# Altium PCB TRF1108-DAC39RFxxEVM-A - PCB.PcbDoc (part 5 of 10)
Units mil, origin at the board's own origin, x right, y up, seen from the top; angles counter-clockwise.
Board outline 4951.22 x 2726.56 mil, 16 copper layers (Top Layer, L2 GND1, L3 PWR1, L4 GND2, L5 PWR2, L6 GND3, L7 Ctrl Signal 1, L8 GND4, L9 GND5, L10 Ctrl Signal 2, L11 GND6, L12 PWR3, L13 GND7, L14 PWR4, L15 GND8, Bottom Layer), stack 80.2 mil thick; 705 components, 433 nets, 3633 pads, 1678 vias.
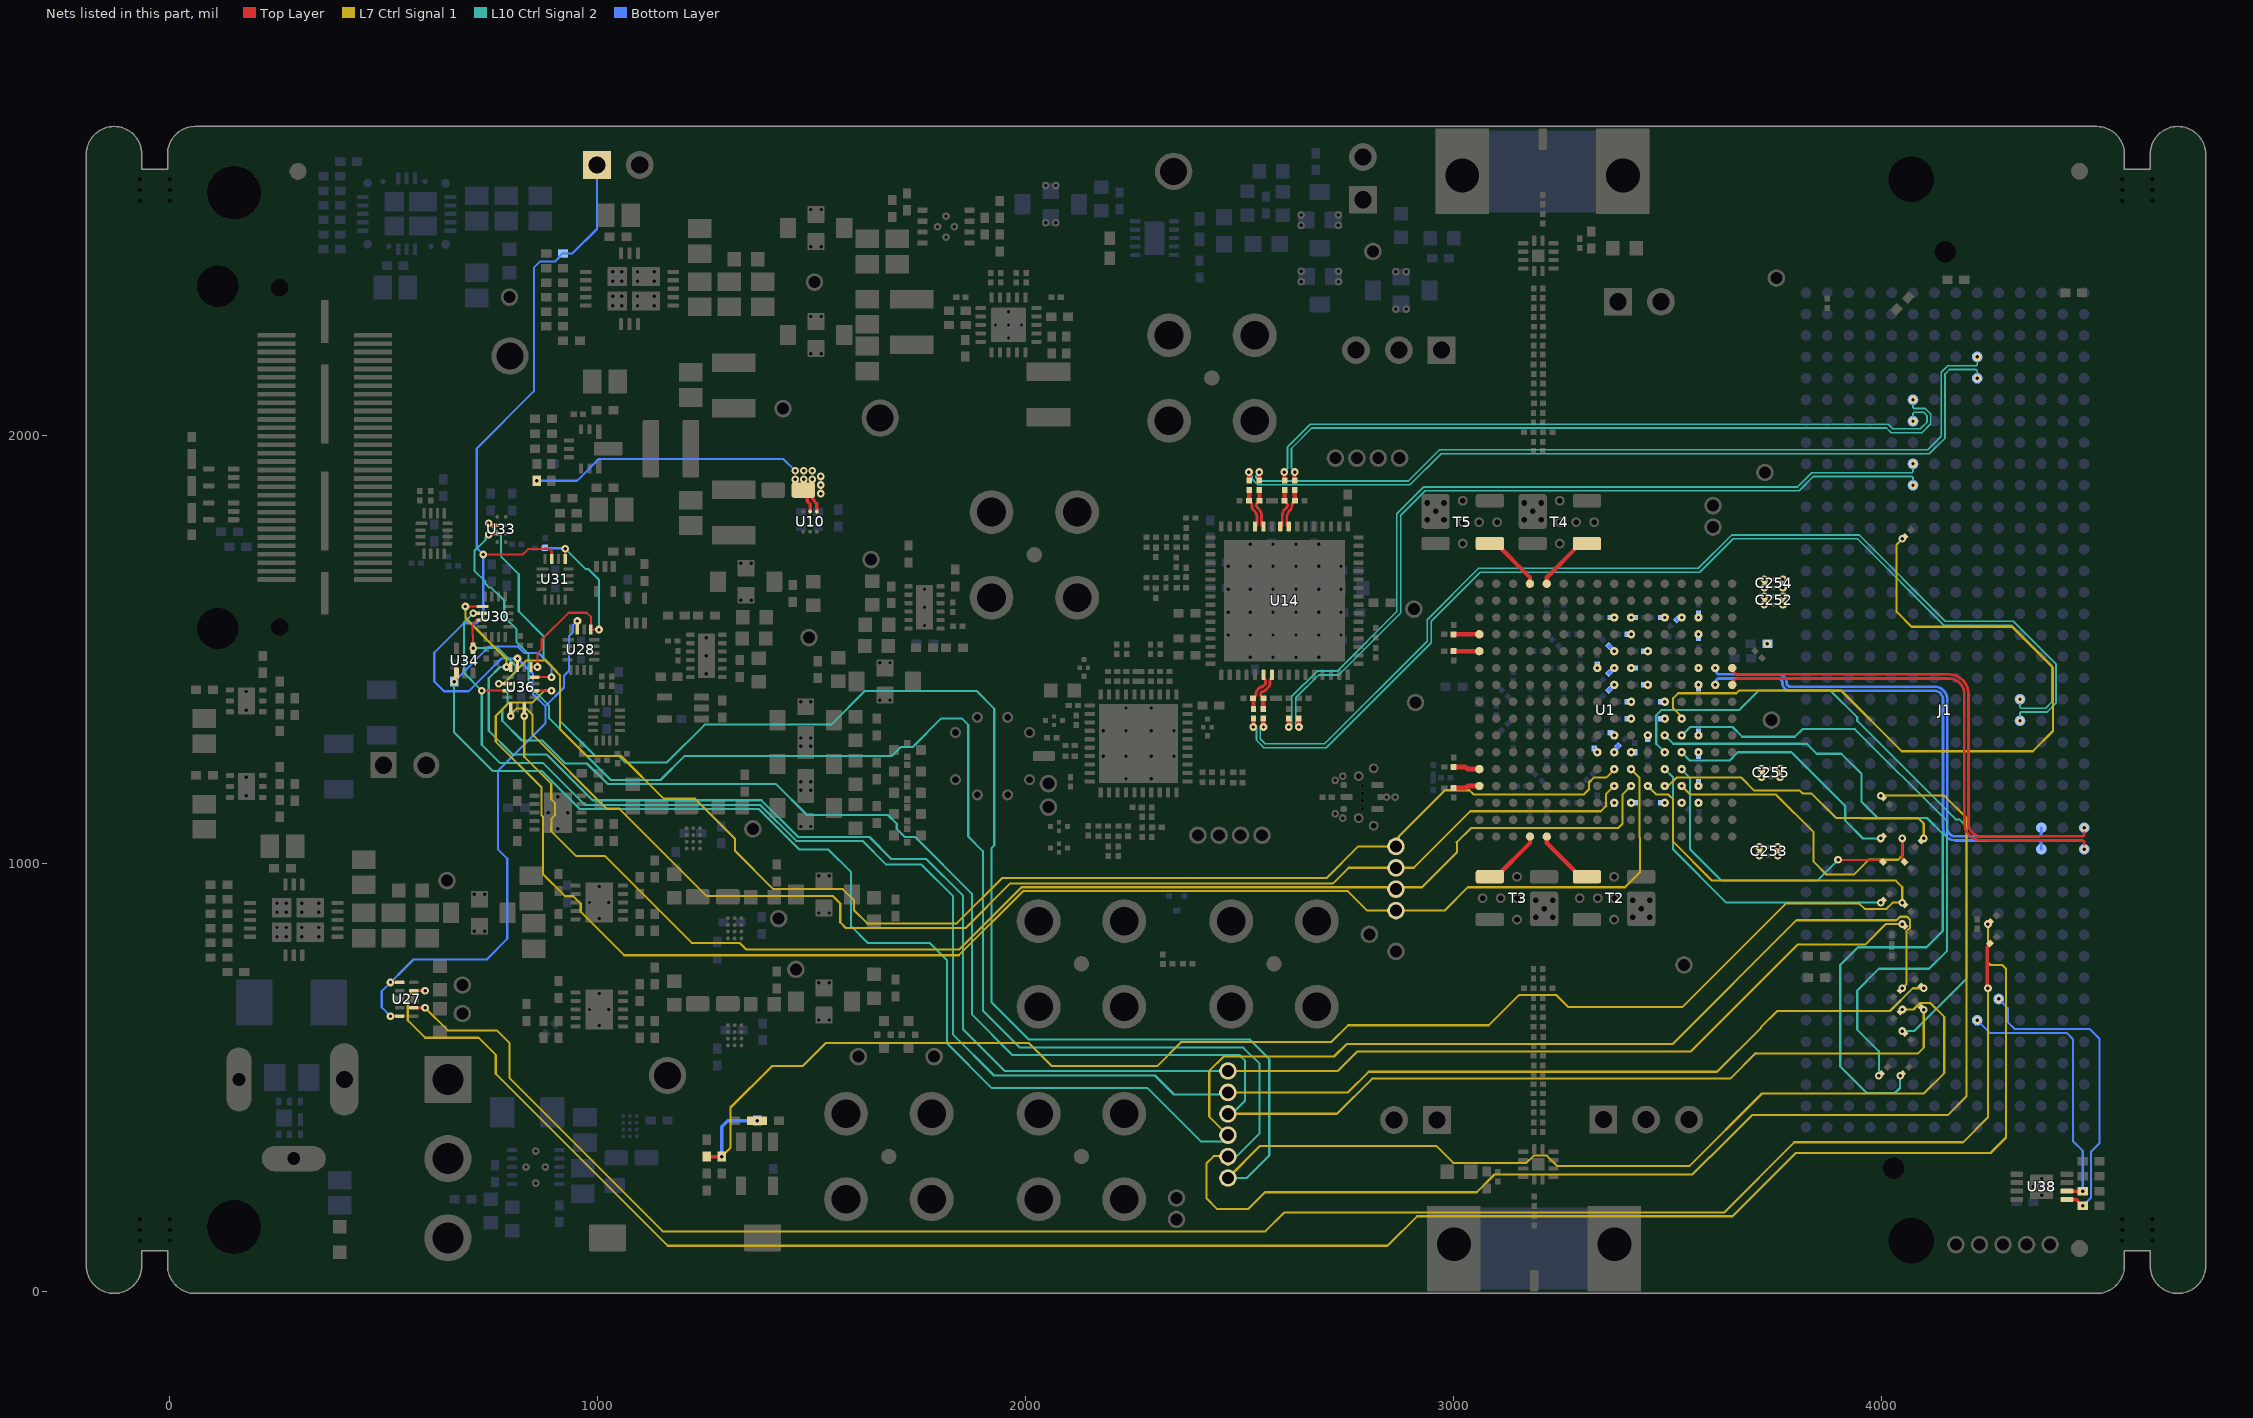
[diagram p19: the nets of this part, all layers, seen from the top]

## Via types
v1: diameter 18, hole 8, Top Layer to Bottom Layer, tented both sides, 1468 vias
v2: diameter 20, hole 10.01, Top Layer to Bottom Layer, 187 vias
v3: diameter 19.68, hole 7.87, Top Layer to Bottom Layer, tented both sides, 16 vias
v4: diameter 19.68, hole 7.87, Top Layer to Bottom Layer, 6 vias
v5: diameter 18/18/18/18/18/18/18/18/18/18/18/18/18/18/18/18 (per signal layer), hole 8, Top Layer to Bottom Layer, tented both sides, 1 vias

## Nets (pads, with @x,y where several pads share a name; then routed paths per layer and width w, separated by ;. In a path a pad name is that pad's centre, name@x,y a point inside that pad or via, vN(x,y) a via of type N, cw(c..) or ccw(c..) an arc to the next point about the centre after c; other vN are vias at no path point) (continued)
14SRX_n: J1.Y26 U1.L1 | length 1194.7
  Top Layer w6.25: U1.L1@3650.36,1456.21 ccw(c3665.17,1456.21) 3665.17,1441.4 4156.63,1441.4 cw(c4156.63,1395.6) 4202.44,1395.6 4202.44,1093.14 ccw(c4232.64,1093.14) 4232.64,1062.93 4467.73,1062.93 ccw(c4467.73,1068.01) 4472.81,1068.01 v1(4472.81,1083.06)
14SRX_p: J1.Y27 U1.K1 | length 1194
  Top Layer w6.25: U1.K1@3650.36,1416.84 cw(c3665.17,1416.84) 3665.17,1431.65 4156.63,1431.65 cw(c4156.63,1395.6) 4192.69,1395.6 4192.69,1116.68 ccw(c4256.18,1116.68) 4193.14,1109.05 cw(c4186.94,1108.34) 4193.19,1108.37 4193.19,1093.14 ccw(c4232.64,1093.14) 4232.64,1053.68 4247.88,1053.68 cw(c4247.85,1047.43) 4248.56,1053.64 ccw(c4256.18,1116.68) 4256.18,1053.18 4467.73,1053.18 cw(c4467.73,1048.1) 4472.81,1048.1 v1(4472.81,1033.06)
15SRX_n: J1.A26 U1.L2 | length 1133.4
  Bottom Layer w6.25: v1(3610.99,1456.21) cw(c3605.56,1450.79) 3613.24,1450.79 3613.24,1447.81 ccw(c3619.64,1447.81) 3615.11,1443.28 ccw(c3619.64,1447.81) 3619.64,1441.4 3757.54,1441.4 cw(c3757.54,1421.3) 3777.64,1421.3 ccw(c3786.15,1421.3) 3786.15,1412.79 4122.81,1412.79 cw(c4122.81,1383.07) 4152.53,1383.07 4152.53,1083.06 ccw(c4172.65,1083.06) 4172.65,1062.93 4363.97,1062.93 ccw(c4363.97,1071.77) 4372.81,1071.77 J1.A26@4372.81,1083.06
15SRX_p: J1.A27 U1.K2 | length 1133.4
  Bottom Layer w6.25: v1(3610.99,1416.84) ccw(c3605.56,1422.27) 3613.24,1422.27 3613.24,1425.25 cw(c3619.64,1425.25) 3615.11,1429.78 cw(c3619.64,1425.25) 3619.64,1431.65 3757.54,1431.65 cw(c3757.54,1421.3) 3767.89,1421.3 ccw(c3786.15,1421.3) 3786.15,1403.04 4122.81,1403.04 cw(c4122.81,1383.07) 4142.78,1383.07 4142.78,1083.06 ccw(c4172.65,1083.06) 4172.65,1053.18 4363.97,1053.18 cw(c4363.97,1044.34) 4372.81,1044.34 J1.A27@4372.81,1033.06
COMM_MUX_CTRL: J12.1 R161.1 U27.1 U27.5 U28.15 U31.15 U36.15 | length 3290.5
  Top Layer w5: v1(515.88,642.95) U27.5@537.69,642.95 ; v1(515.88,721.7) U27.1@537.69,721.7 ; v1(732.62,1721.42) 825.06,1721.42 837.6,1733.97 886.77,1733.97 892.57,1728.16 U31.15@892.57,1711.04 ; U28.15@952.57,1546.04 v1(952.57,1566.04)
  Bottom Layer w5: v1(515.88,642.95) 495.4,663.44 495.4,701.21 569.45,775.27 740.44,775.27 788.49,823.32 788.49,1010.8 766.73,1032.55 766.73,1215.72 877.57,1326.56 877.57,1366.89 ; v1(952.57,1566.04) 942.32,1555.79 942.32,1539.62 932.89,1530.18 932.89,1449.53 921.32,1437.97 921.32,1410.88 877.57,1367.13 877.57,1366.89 ; J12.1@998.12,2631.37 998.12,2481.96 940.79,2424.63 R161.1@919.01,2424.63 917.04,2424.63 909.7,2417.29 909.7,2415.32 900.67,2406.29 865.51,2406.29 850.92,2391.69 850.92,2102.75 717.41,1969.25 717.41,1736.63 v1(732.62,1721.42) 732.62,1576.25 717.18,1560.81 687.05,1560.81 618.06,1491.83 618.06,1424.68 640.74,1402.01 698.41,1402.01 752.45,1456.04 752.54,1456.04 775.04,1478.54 v1(812.57,1478.54) 848.95,1442.16 848.95,1395.51 877.57,1366.89
COMM_MUX_EN: R159.1 R162.2 U28.13 U31.13 U36.13 | length 579.8
  Top Layer w5: U36.13@844.07,1458.54 v1(859.07,1458.54) 859.07,1490.07 869.3,1500.3 869.3,1522.88 931.91,1585.49 974.7,1585.49 984.07,1576.12 U28.13@984.07,1546.04 v1(1003,1546.04) ; v1@921.14,1738.04 v1(924.07,1735.11) U31.13@924.07,1711.04
  L10 Ctrl Signal 2 w5: v1(924.07,1735.11) 972.01,1687.17 978.36,1687.17 1003,1662.52 v1(1003,1546.04)
  Bottom Layer w5: R159.1@875.57,1736.04 923.14,1736.04 v1(924.07,1735.11)
DAC_ALARM: R209.1 U1.H4 | length 1772.9
  Top Layer w5: R209.1@4047.5,1757.75 v1(4047.81,1758.06)
  L7 Ctrl Signal 1 w5: v1(3532.25,1338.1) 3532.25,1341.62 3527.65,1346.22 3527.65,1346.84 3512.48,1362.01 3512.48,1385.59 3524.13,1397.24 3660.24,1397.24 3666.78,1403.79 3904.73,1403.79 4046.68,1261.84 4352.8,1261.84 4400,1309.04 4400,1456.62 4303.96,1552.66 4069.38,1552.66 4034.47,1587.57 4034.47,1744.71 v1(4047.81,1758.06)
DAC_C\S\: PP38.1 U1.E7 U36.10 | length 3629.7
  Top Layer w5: U36.10@851.94,1403.42 v1(891.94,1403.42)
  L7 Ctrl Signal 1 w5: v1(891.94,1403.42) 875.44,1403.41 847.89,1375.86 793.35,1375.86 761.73,1344.24 761.73,1284.15 868.91,1176.96 868.91,1112.07 871.94,1109.04 871.94,975.03 924.01,922.96 942.81,922.96 960.24,905.53 960.24,886.74 1061.87,785.11 1843.75,785.11 1993.73,935.08 2752.17,935.08 2797.78,889.47 PP38.1@2864.85,889.47 2978.41,889.47 3032.97,944.03 3400.03,944.03 3435,979 3435,1060 ; v1(3414.14,1219.99) 3433.91,1200.22 3433.91,1188.74 3433.74,1188.57 3433.74,1060
DAC_CIPO: PP37.1 U1.D7 U36.7 | length 3171.6
  Top Layer w5: v1(828.32,1344.05) U36.7@828.32,1364.05
  L7 Ctrl Signal 1 w5: v1(828.32,1344.05) 828.32,1249 891.55,1185.77 891.55,1149.47 899.79,1141.24 899.79,1112.07 891.94,1104.22 891.94,1087.85 891.55,1087.46 891.55,1074.67 948.95,1017.27 1016.37,1017.27 1219.54,814.11 1331.22,814.11 1346.89,798.43 1844.35,798.43 1990,944.08 2925.53,944.08 3007.54,1026.09 3007.54,1049 ; 3007,1049 3040.11,1082.11 3383.77,1082.11 3394.54,1092.88 3394.54,1161.02 v1(3414.14,1180.62)
DAC_CLK_n: C135.2 C140.1 U1.E16 | length 61.3
  Top Layer w11.5: C135.2@2999.81,1224.99 3024.49,1224.99 cw(c3024.49,1218.67) 3028.96,1223.14 ccw(c3036.56,1230.74) 3036.56,1219.99 U1.E16@3059.81,1219.99
DAC_CLK_p: C134.2 C138.1 U1.D16 | length 61.3
  Top Layer w11.5: C134.2@2999.81,1175.62 3024.49,1175.62 ccw(c3024.49,1181.94) 3028.96,1177.47 cw(c3036.56,1169.87) 3036.56,1180.62 U1.D16@3059.81,1180.62
DAC_COPI: PP36.1 U1.D8 U36.5 | length 3028.6
  Top Layer w5: v1(796.82,1344.05) U36.5@796.82,1364.05
  L7 Ctrl Signal 1 w5: v1(796.82,1344.05) cw(c807.09,1344.05) 799.83,1351.31 810.5,1361.98 832.31,1361.98 847.99,1346.3 847.99,1300.01 1020.53,1127.46 1050.27,1127.46 1253.73,924 1548.65,924 1566.49,906.16 1566.49,862.1 1579.98,848.62 1859.36,848.62 1963.82,953.08 2718.01,953.08 2754.4,989.47 PP36.1@2864.85,989.47 2906.33,989.47 3038.52,1121.65 3343.52,1121.65 3355.17,1133.3 3355.17,1161.17 v1@3376,1182
  other v1: 3374.77,1180.62
DAC_R\E\S\E\T\: C171.2 R170.1 R171.1 R173.1 R174.1 R220.1 U1.D6 | length 4141
  Top Layer w5: v1@4047.5,908.36 v1(4047.81,908.06)
  Top Layer w8: R170.1@1254.63,314.72 v1(1289.63,314.72) ; R174.1@1360.42,398.96 R173.1@1384.04,398.96
  L7 Ctrl Signal 1 w5: v1(1289.63,314.72) 1310.37,335.46 1310.37,429.37 1407.2,526.2 1478.3,526.2 1532.42,580.32 2007.23,580.32 2061.35,526.2 2307.22,526.2 2363.34,582.32 2713.8,582.32 2753.24,621.76 3081.76,621.76 3152,692 3240,692 3268,664 3534,664 3775.67,905.67 3947.63,905.67 3959.74,893.56 4010.8,893.56 4025.3,908.06 v1(4047.81,908.06) 4047.81,944.01 4032.35,959.46 3603.16,959.46 3512.48,1050.15 3512.48,1149.37 3501,1160.85 3473.28,1160.85 v1(3453.51,1180.62)
  Bottom Layer w8: v1(1289.63,314.72) 1289.63,384.84 1303.74,398.96 v1(1372.23,398.96)
DAC_SCLK: PP35.1 U1.E8 U36.2 | length 3184.4
  Top Layer w5: v1(768.95,1419.17) U36.2@788.95,1419.17
  L7 Ctrl Signal 1 w5: v1(768.95,1419.17) 770.74,1420.95 780.5,1420.95 833.58,1474.04 878.16,1474.04 900.73,1451.47 900.73,1450.41 911.59,1439.56 911.59,1313.67 974.47,1250.79 1054.22,1250.79 1154.2,1150.81 1227.21,1150.81 1320.57,1057.46 1320.57,1029.38 1410.4,939.55 1572.83,939.55 1598.77,913.61 1598.77,890.59 1629.63,859.73 1839.11,859.73 1944.85,965.46 2703.01,965.46 2777.02,1039.47 PP35.1@2864.85,1039.47 2871.24,1045.86 2871.24,1062.47 2979.46,1170.69 3036.47,1170.69 3046.14,1161.02 3304.15,1161.02 3315.71,1172.59 3315.71,1188.66 3327.28,1200.22 3343.52,1200.22 3356.22,1200.22 3374.77,1218.77 v1(3374.77,1219.99)
DAC_SYSREF_n: C73.2 C76.1 U1.N16 | length 60
  Top Layer w10: C73.2@2999.81,1534.95 U1.N16@3059.81,1534.95
DAC_SYSREF_p: C74.2 C75.1 U1.M16 | length 60
  Top Layer w10: C74.2@2999.81,1495.58 U1.M16@3059.81,1495.58
DAC_TXEN0: R216.1 U1.D5 | length 692.5
  L7 Ctrl Signal 1 w5: v1(3492.88,1180.62) 3495.36,1183.11 3503.54,1183.11 3520.82,1200.39 3671.38,1200.39 3701.92,1169.85 3808.29,1169.85 3814.69,1163.46 3835.38,1163.46 3892.8,1106.04 3953.8,1106.04 3954.6,1105.24 4085.54,1105.24 4097.81,1092.98 v1(4097.81,1058.06)
DAC_TXEN1: R218.1 U1.D4 | length 757
  Top Layer w5: 4047.5,1008.36 R218.1@4047.81,1008.06 ; v1(4047.81,1058.06) 4047.81,1013.24 4052.52,1008.54 R218.1@4052.52,1003.35
  L7 Ctrl Signal 1 w5: v1(3532.25,1180.62) 3552.02,1160.85 3752.25,1160.85 3840.58,1072.52 3840.58,1003.9 3870.9,973.59 3934.46,973.59 3969.14,1008.27 4038.03,1008.27 4047.81,1018.04 v1(4047.81,1058.06)
DACOUTA_n: T3.1 U1.A13 | length 141.4
  Top Layer w10: T3.1@3084.22,968.59 3098.99,968.59 3177.92,1047.51 U1.A13@3177.92,1062.51
DACOUTA_p: T2.1 U1.A12 | length 141.4
  Top Layer w10: U1.A12@3217.29,1062.51 3217.29,1047.51 3296.21,968.59 T2.1@3310.99,968.59
DACOUTB_n: T5.1 U1.T13 | length 141.4
  Top Layer w10: T5.1@3084.22,1746.99 3098.99,1746.99 3177.92,1668.06 U1.T13@3177.92,1653.06
DACOUTB_p: T4.1 U1.T12 | length 141.4
  Top Layer w10: U1.T12@3217.29,1653.06 3217.29,1668.06 3296.21,1746.99 T4.1@3310.99,1746.99
DCLKOUT2_n: C91.2 R75.2 U14.55 | length 92.7
  Top Layer w6.5: R75.2@2555.71,1385.46 cw(c2555.71,1387.37) 2554.37,1386.02 2550.83,1389.56 cw(c2555.96,1394.7) 2548.7,1394.7 cw(c2555.96,1394.7) 2550.83,1399.83 2550.9,1399.9 cw(c2554.78,1396.02) 2554.78,1401.51 ccw(c2554.78,1407.01) 2558.66,1403.12 2567.35,1411.81 ccw(c2559.97,1419.19) 2570.41,1419.19 2570.41,1425.73 cw(c2578.25,1425.73) 2572.71,1431.28 ccw(c2567.16,1436.82) 2575,1436.82 U14.55@2575,1440.46
  Top Layer w10: C91.2@2554.93,1360.46 R75.2@2554.93,1383.56
DCLKOUT2_p: C90.2 R74.2 U14.54 | length 92.8
  Top Layer w6.5: R74.2@2531.19,1385.46 ccw(c2531.19,1387.37) R74.2@2532.52,1386.02 ; R74.2@2532.53,1386.02 2535.09,1388.58 ccw(c2527.57,1396.09) 2538.2,1396.09 2538.2,1396.87 cw(c2550.71,1396.87) 2541.85,1405.71 ; 2541.86,1405.72 2546.55,1410.4 cw(c2550.43,1406.52) 2550.43,1412.01 ccw(c2550.43,1417.51) 2554.31,1413.62 2559.91,1419.22 2559.91,1425.73 ccw(c2552.07,1425.73) 2557.61,1431.28 cw(c2563.16,1436.82) 2555.32,1436.82 U14.54@2555.32,1440.46
  Top Layer w10: C90.2@2531.97,1360.46 R74.2@2531.97,1383.56
DCLKOUT4_n: C85.2 R79.2 U14.25 | length 94.5
  Top Layer w6.5: U14.25@2594.69,1786.92 ccw(c2594.69,1791.51) 2599.28,1791.51 2599.28,1812.62 cw(c2619.74,1812.62) 2605.27,1827.09 2608.62,1830.44 ccw(c2602.22,1836.83) 2611.27,1836.83 ccw(c2602.22,1836.83) R79.2@2608.63,1843.22 ; R79.2@2604.14,1846.92 cw(c2604.14,1845.02) R79.2@2605.48,1846.37 ; R79.2@2605.48,1846.36 R79.2@2608.62,1843.23
  Top Layer w10: R79.2@2604.14,1846.92 ccw(c2602.24,1848.82) 2604.92,1848.82 C85.2@2604.92,1871.92
DCLKOUT4_p: C84.2 R78.2 U14.24 | length 94.2
  Top Layer w6.5: U14.24@2614.37,1786.92 cw(c2614.37,1791.51) 2609.78,1791.51 2609.78,1808.27 cw(c2630.24,1808.27) 2615.77,1822.74 2617.58,1824.55 ccw(c2607.47,1834.66) 2621.77,1834.66 2621.77,1836.09 cw(c2632.59,1836.09) 2624.94,1843.75 R78.2@2627.55,1846.36 ; R78.2@2627.56,1846.37 cw(c2628.9,1845.02) R78.2@2628.9,1846.92
  Top Layer w10: C84.2@2628.11,1871.92 2628.11,1848.82 ccw(c2630.8,1848.82) R78.2@2628.9,1846.92
DCLKOUT6_n: C87.2 R81.2 U14.28 | length 89.5
  Top Layer w6.5: R81.2@2525.07,1843.75 cw(c2517.41,1836.09) 2528.24,1836.09 2528.24,1834.66 ccw(c2542.54,1834.66) 2532.43,1824.55 2534.23,1822.74 cw(c2519.76,1808.27) 2540.23,1808.27 2540.23,1791.51 cw(c2535.63,1791.51) U14.28@2535.63,1786.92
  Top Layer w10: C87.2@2521.9,1871.92 2521.9,1847.7 ccw(c2523.78,1847.7) R81.2@2522.44,1846.38
DCLKOUT6_p: C86.2 R80.2 U14.27 | length 94.5
  Top Layer w6.5: R80.2@2544.53,1846.36 2541.38,1843.22 ccw(c2547.79,1836.83) 2538.74,1836.83 ccw(c2547.79,1836.83) 2541.39,1830.44 2544.73,1827.09 cw(c2530.26,1812.62) 2550.73,1812.62 2550.73,1791.51 ccw(c2555.32,1791.51) U14.27@2555.32,1786.92 ; R80.2@2544.53,1846.37 cw(c2545.87,1845.02) R80.2@2545.87,1846.92
  Top Layer w10: C86.2@2545.08,1871.92 cw(c2543.18,1870.02) 2545.87,1870.02 R80.2@2545.87,1846.92
DVDD: C190.2 C191.2 C192.2 C193.2 C194.2 C195.2 C196.2 C197.2 C198.2 C199.2 C200.2 C201.2 C202.2 C203.2 C204.2 C205.2 C206.2 C207.2 C208.2 C209.2 C210.2 C211.2 C212.2 C227.2 C228.2 C229.2 C230.2 C231.2 C232.2 C233.2 C234.2 C235.2 C252.1 C252.3 C253.1 C253.3 C254.1 C254.3 C255.1 C255.3 R36.1 R40.2 R45.2 U1.C3 U1.C4 U1.C5 U1.C7 U1.C8 U1.D3 U1.F3 U1.F7 U1.F8 U1.F9 U1.G3 U1.G6 U1.G8 U1.H5 U1.H7 U1.J5 U1.J7 U1.K3 U1.K6 U1.K8 U1.L3 U1.L7 U1.L8 U1.L9 U1.M6 U1.M8 U1.N3 U1.N7 U1.P3 U1.P4 U1.P5 U1.P7 U1.P8 U10.D1 U10.D2 | length 1226.2
  Top Layer w8: U10.D2@1496.1,1821.8 1496.1,1839.1 1489.49,1845.71 1489.49,1862.66 R36.1@1480.35,1871.8 1488.06,1871.8 1502.02,1857.84 1502.02,1850.14 1511.85,1840.31 U10.D1@1511.85,1821.8
  Top Layer w10: v1(3713.63,1018.04) 3714.72,1019.14 3714.72,1027.14 C253.3@3715.63,1028.04 3714.72,1028.95 3714.72,1036.95 v1(3713.63,1038.04) ; v1(3718.93,1201.1) 3720.02,1202.19 3720.02,1210.19 C255.3@3720.93,1211.1 3720.02,1212 3720.02,1220 v1(3718.93,1221.1) ; v1(3725.49,1604.22) 3726.59,1605.31 3726.59,1613.31 C252.3@3727.49,1614.22 3726.59,1615.12 3726.59,1623.12 v1(3725.49,1624.22) ; v1(3725.49,1643.9) 3726.59,1645 3726.59,1653 C254.3@3727.49,1653.9 3726.59,1654.81 3726.59,1662.81 v1(3725.49,1663.9) ; v1(3757,1018.04) 3755.9,1019.14 3755.9,1027.14 C253.1@3755,1028.04 3755.9,1028.95 3755.9,1036.95 v1(3757,1038.04) ; v1(3762.3,1201.1) 3761.2,1202.19 3761.2,1210.19 C255.1@3760.3,1211.1 3761.2,1212 3761.2,1220 v1(3762.3,1221.1) ; v1(3768.86,1604.22) 3767.77,1605.31 3767.77,1613.31 C252.1@3766.86,1614.22 3767.77,1615.12 3767.77,1623.12 v1(3768.86,1624.22) ; v1(3768.86,1643.9) 3767.77,1645 3767.77,1653 C254.1@3766.86,1653.9 3767.77,1654.81 3767.77,1662.81 v1(3768.86,1663.9)
  Bottom Layer w5: v1(857.91,1893.82) 951.95,1893.82 1002.58,1944.45 1433.71,1944.45 v1(1461.35,1916.8) ; C200.2@3328.4,1268.02 3335.4,1261.02 v1(3335.4,1259.36) ; v1(3335.4,1456.21) C196.2@3335.4,1464.87 ; C201.2@3366.1,1298.73 v1(3374.77,1298.73) ; C235.2@3366.11,1574.32 v1(3374.77,1574.32) ; C228.2@3405.48,1338.1 v1(3414.14,1338.1) ; C194.2@3405.48,1377.47 v1(3414.14,1377.47) ; C232.2@3405.48,1534.95 v1(3414.14,1534.95) ; v1(3414.14,1141.25) C210.2@3422.8,1141.25 ; v1(3414.14,1259.36) C192.2@3420.74,1259.36 ; v1(3414.14,1456.21) C230.2@3422.8,1456.21 ; v1(3414.14,1574.32) C199.2@3422.8,1574.32 ; C203.2@3444.85,1416.84 v1(3453.51,1416.84) ; C195.2@3444.85,1495.58 v1(3453.51,1495.58) ; C193.2@3453.51,1290.07 v1(3453.51,1298.73) ; C208.2@3484.22,1141.25 v1(3492.88,1141.25) ; C229.2@3484.22,1338.1 v1(3492.88,1338.1) ; C202.2@3484.22,1377.47 v1(3492.88,1377.47) ; C234.2@3484.22,1574.32 v1(3492.88,1574.32) ; v1(3571.62,1141.25) C211.2@3573.62,1141.25 ; v1(3571.62,1180.62) C212.2@3571.62,1189.28 ; C207.2@3571.62,1250.7 v1(3571.62,1259.36) ; v1(3571.62,1298.73) C206.2@3571.62,1307.39 ; C209.2@3571.62,1408.18 v1(3571.62,1416.84) ; C197.2@3571.62,1526.29 v1(3571.62,1534.95) ; v1(3571.62,1574.32) C233.2@3571.62,1582.99
  Bottom Layer w10: C204.2@3362.88,1404.95 v1(3374.77,1416.84) ; C231.2@3362.88,1444.32 v1(3374.77,1456.21) ; C205.2@3362.88,1507.47 v1(3374.77,1495.58) ; v1(3374.77,1259.36) 3376.3,1260.89 3376.3,1265.06 3383.77,1272.53 C227.2@3383.77,1274.36 ; C198.2@3521.25,1569.32 3523.09,1569.32 3526.55,1572.79 3530.72,1572.79 v1(3532.25,1574.32)
  other v1: 3374.77,1141.25 3532.25,1141.25 3571.62,1456.21 3732.72,1512.58 1521.35,1863.8 1521.35,1883.8 1461.35,1896.8 1481.35,1896.8 1501.35,1896.8 1521.35,1903.8 1481.35,1916.8 1501.35,1916.8
FMC_C\S\_DAC: PP34.1 R163.2 R225.1 U34.1 U36.12 | length 5016.1
  Top Layer w5: U36.12@851.94,1434.91 v1(891.94,1434.91) ; R225.1@4043.12,703.35 v1(4047.83,708.06)
  Top Layer w8: v1@664.58,1419.4 664.58,1422.11 669.58,1427.11 U34.1@669.58,1444.4
  L7 Ctrl Signal 1 w5: PP34.1@2472.23,364.83 2428.82,408.24 2428.82,515.12 2462.32,548.62 2720.22,548.62 2749.59,578 3511.39,578 3800.44,867.06 4034.15,867.06 4042.34,875.24 4058.71,875.24 4065.65,868.29 4065.65,849.59 4057.31,841.25 4057.31,717.54 v1(4047.83,708.06)
  L10 Ctrl Signal 2 w5: v1(664.58,1424.4) 664.58,1305.63 754.32,1215.88 868.8,1215.88 957.87,1126.82 1376.48,1126.82 1471.29,1032 1539,1032 1592.02,978.98 1592.02,852.69 1630.98,813.73 1775.32,813.73 1816.19,772.86 1816.19,578.81 1919.74,475.26 2284.18,475.26 2409.61,349.83 PP34.1@2472.23,349.83
  Bottom Layer w5: v1(664.58,1424.4) 664.58,1426.37 671.92,1433.71 673.65,1433.71 746.66,1506.72 812.58,1506.72 828.08,1491.22 861.72,1491.22 891.94,1461.01 v1(891.94,1434.91)
FMC_C\S\_LMK: PP33.1 R211.1 U33.C1 | length 6204.6
  Top Layer w8: v1@745.34,1765.04 748.05,1765.04 753.05,1770.04 U33.C1@765.34,1770.04 ; v1(3997.81,1158.06) R211.1@4002.52,1153.35
  L7 Ctrl Signal 1 w5: PP33.1@2472.23,314.83 2471.13,315.93 2439.31,315.93 2422.39,299.01 2422.39,217.32 2447.72,192 2519.18,192 2558.77,231.6 3053.6,231.6 3095,273 3557,273 3598.5,314.5 ; 3599,314 3696.58,411.58 4153.85,411.58 4197.81,455.54 4197.81,1106.04 4145.8,1158.06 v1(3997.81,1158.06)
  L10 Ctrl Signal 2 w5: v1(745.34,1768.04) 738.52,1761.22 738.52,1756.24 711.8,1729.51 711.8,1683.79 738.07,1657.52 738.07,1652.53 746.56,1644.04 751.55,1644.04 781.54,1614.05 781.54,1575.34 810.47,1546.41 810.47,1516.28 838.57,1488.18 838.57,1415.64 886.46,1367.74 886.46,1338.8 1030.69,1194.57 1146.57,1194.57 1203,1251 1687.49,1251 1708.25,1271.76 1735.63,1271.76 1802.39,1338.52 1850.47,1338.52 1865.71,1323.29 1865.71,1062.49 1899.73,1028.47 1899.73,656.27 1986.61,569.39 2508.36,569.39 2546.39,531.37 2546.39,368.99 PP33.1@2472.23,294.83
FMC_C\S\_LMX: PP32.1 R227.1 U33.B1 | length 5506
  Top Layer w8: v1(745.54,1794.52) 748.25,1794.52 753.25,1789.52 U33.B1@765.54,1789.52
  L7 Ctrl Signal 1 w5: PP32.1@2472.3,264.9 2547.23,339.83 2959,339.83 2998.83,300 3170,300 3187,317 3217,317 3241,293 3551,293 3719,461 ; 3719,462.56 4098.62,462.56 4145.8,509.74 4145.8,641.32 4113.49,673.63 4089.31,673.63 4073.94,658.27 4073.85,658.36 v1(4048.12,658.36)
  L10 Ctrl Signal 2 w5: v1(745.54,1794.52) 774.41,1765.66 774.41,1716.44 815.38,1675.46 815.38,1588.81 873.45,1530.74 873.45,1477.7 911.59,1439.56 911.59,1333.22 994.02,1250.79 1049.21,1250.79 1064.53,1235.47 1161.27,1235.47 1249.8,1324 1545.53,1324 1623.88,1402.35 1885.42,1402.35 1926.52,1361.26 1926.52,1041.89 1920,1035.37 1920,675.52 2007.2,588.32 2523.32,588.32 2568.82,542.82 2568.82,317.26 2516.39,264.83 PP32.1@2472.23,264.83
FMC_CIPO: PP26.1 R226.1 U30.3 U34.4 | length 4500.7
  Top Layer w5: v1(708.95,1502.67) 708.95,1532.12 707.71,1533.37 707.71,1558.99 U30.3@717.14,1568.42
  Top Layer w8: R226.1@4093.11,662.76 v1(4097.81,658.06)
  L7 Ctrl Signal 1 w5: PP26.1@2472.23,414.83 2727.29,414.83 2809.47,497 3646,497 3706,557 ; 3706,555.25 4083.66,555.25 4097.81,569.41 v1(4097.81,658.06)
  L10 Ctrl Signal 2 w5: v1(708.95,1502.67) 767.33,1502.67 808,1462 808,1446.91 789.07,1427.97 789.07,1371.58 776.97,1359.48 776.97,1333.03 823,1287 870,1287 923.83,1233.17 975.08,1233.17 1022.69,1185.57 1416.11,1185.57 1488.82,1112.86 1678.34,1112.86 1698.69,1092.51 1698.69,1080.31 1717.68,1061.32 1741.85,1061.32 1873.98,929.19 1873.98,646.99 1968.83,552.14 2499.3,552.14 2511.89,539.55 2511.89,444.49 PP26.1@2472.23,404.83
FMC_COPI: PP28.1 R224.1 U30.2 U36.3 | length 4417.7
  Top Layer w5: v1(708.95,1584.17) U30.2@728.95,1584.17 ; v1(728.95,1403.42) U36.3@788.95,1403.42
  Top Layer w8: R224.1@4093.11,712.76 v1(4097.81,708.06)
  L7 Ctrl Signal 1 w5: PP28.1@2472.23,464.83 2752.83,464.83 2801,513 3615,513 3718,616 ; 3717.4,616.6 3755.63,654.84 4019.22,654.84 4072.44,708.06 v1(4097.81,708.06)
  L10 Ctrl Signal 2 w5: v1(708.95,1584.17) 687.45,1562.67 687.45,1444.92 v1(728.95,1403.42) 728.95,1277.09 772.04,1234 872.47,1234 970.65,1135.82 1380.2,1135.82 1463.7,1052.32 1618.68,1052.32 1674.01,996.99 1756.37,996.99 1830.39,922.97 1830.39,599.61 1925.75,504.25 2302.05,504.25 2346.48,459.83 PP28.1@2472.23,459.83
FMC_F\R\C\S\: R229.1 U1.G4 | length 1506.4
  Top Layer w5: v1@3992.8,503.04 v1(3993.11,503.35)
  L10 Ctrl Signal 2 w5: v1(3532.25,1298.73) 3552.02,1318.5 3650.93,1318.5 3673.82,1295.61 3796.85,1295.61 3814.69,1313.46 3937.05,1313.46 4152.53,1097.98 4152.53,795.73 4110.35,753.56 3993.11,753.56 3942.41,702.86 3942.41,611.43 3993.11,560.74 v1(3993.11,503.35)
FMC_FRCLK: R212.1 U1.F4 | length 585.6
  Top Layer w5: v1@3997.5,1057.75 v1(3997.81,1058.06)
  L10 Ctrl Signal 2 w5: v1(3532.25,1259.36) 3551.85,1239.76 3644.11,1239.76 3663.71,1259.36 3789.01,1259.36 3914.59,1133.78 3914.59,1099.63 3956.16,1058.06 v1(3997.81,1058.06)
FMC_FRDI0: R217.1 U1.E4 | length 698.5
  Top Layer w5: v1(3897.81,1008.06) 3992.62,1008.06 3997.33,1003.35 R217.1@4002.52,1003.35
  L10 Ctrl Signal 2 w5: v1(3532.25,1219.99) 3532.25,1218.68 3552.02,1198.91 3552.02,1161.19 3551.85,1161.02 3551.85,1032.99 3625.37,959.46 3849.22,959.46 v1(3897.81,1008.06)
FMC_FRDI1: R219.1 U1.E5 | length 733
  Top Layer w5: v1@3997.5,907.75 v1(3997.81,908.06)
  L10 Ctrl Signal 2 w5: v1(3492.88,1219.99) 3512.18,1200.69 3512.18,1189.04 3512.48,1188.74 3512.48,1033.06 3512.48,1032.36 3636.79,908.06 v1(3997.81,908.06)
FMC_FRDI2: R228.1 U1.F5 | length 1536.8
  Top Layer w5: v1@4047.5,608.36 v1(4047.81,608.06)
  L10 Ctrl Signal 2 w5: v1(3492.88,1259.36) 3473.11,1279.13 3473.11,1346.22 3484.76,1357.87 3666.42,1357.87 3712.34,1403.79 3879.8,1403.79 3942.41,1341.17 3942.41,1332.65 4172.4,1102.66 4180.93,1102.66 4197.81,1085.77 4197.81,730.34 4075.53,608.06 v1(4047.81,608.06)
FMC_FRDI3: R230.1 U1.G5 | length 1718.7
  Top Layer w5: v1@4042.8,503.04 v1(4043.11,503.35)
  L10 Ctrl Signal 2 w5: v1(3492.88,1298.73) 3512.48,1279.13 3824.58,1279.13 3847.66,1256.06 3905.54,1256.06 3952.58,1209.02 3952.58,1143.94 3990.66,1105.86 4105.51,1105.86 4142.41,1068.96 4142.41,841.91 4104.44,803.94 3944.16,803.94 3902.78,762.56 3902.78,525.37 3964.69,463.46 4030.93,463.46 4042.41,474.94 4042.41,502.66 v1(4043.11,503.35)
FMC_I2C_SCL: R205.1 U27.9 | length 4749.2
  Top Layer w6: U27.9@570.56,702.01 v1(596.56,702.01)
  Top Layer w8: v1(4247.81,858.06) R205.1@4252.52,862.76
  L7 Ctrl Signal 1 w5: v1(596.56,702.01) 569.74,702.01 556.06,688.33 556.06,633.35 597.09,592.32 721.78,592.32 761.73,552.37 761.73,508.17 1163.56,106.34 2845.25,106.34 2914.23,175.33 3651.22,175.33 3798.95,323.06 4253.88,323.06 4290.24,359.41 4290.24,753.56 4281.24,762.56 4253.88,762.56 4247.81,768.63 v1(4247.81,858.06)
FMC_I2C_SDA: R207.1 U27.7 | length 4461.2
  Top Layer w6: U27.7@570.56,662.64 v1(596.56,662.64)
  Top Layer w8: v1(4247.81,708.06) 4246.77,709.09 4246.77,803.77 4252.52,809.51 R207.1@4252.52,812.76
  L7 Ctrl Signal 1 w5: v1(596.56,662.64) 649.47,609.73 764.06,609.73 794.1,579.69 794.1,498.02 1152.03,140.09 2559.38,140.09 2603.62,184.33 3631.51,184.33 3795.5,348.32 4190,348.32 4247.81,406.13 v1(4247.81,708.06)
FMC_SCLK: PP30.1 R222.1 U30.1 U36.16 | length 4369.3
  Top Layer w5: v1(690.92,1599.91) U30.1@730.92,1599.91 ; v1(786.82,1458.54) U36.16@796.82,1458.54
  Top Layer w8: v1(4047.81,858.06) R222.1@4052.52,853.35
  L7 Ctrl Signal 1 w5: v1(690.92,1599.91) 690.92,1572.95 786.82,1477.05 v1(786.82,1458.54) ; PP30.1@2472.23,514.83 2728.85,514.83 2774.02,560 3552.91,560 3802.89,809.98 3960.98,809.98 4009.06,858.06 v1(4047.81,858.06)
  L10 Ctrl Signal 2 w5: v1(786.82,1458.54) 771.58,1458.54 745.54,1432.5 745.54,1309.64 801.05,1254.13 881.14,1254.13 987.91,1147.36 1382.4,1147.36 1468.44,1061.32 1634.79,1061.32 1686.33,1009.79 1768.21,1009.79 1853,925 1853,612.72 1950.89,514.83 PP30.1@2472.23,514.83
FPGA_CORECLK_n: C85.1 J1.G7 | length 1679.7
  Top Layer w10: v1(2604.19,1913.97) 2604.69,1913.97 C85.1@2604.69,1893.97
  L10 Ctrl Signal 2 w4: v1(2604.19,1913.97) 2604.19,1915.84 2611.67,1923.31 2611.67,1972.85 2664.82,2026 4014.73,2026 4025.73,2015 4090,2015 4105.51,2030.51 4105.51,2045.86 4097.81,2053.56 4075.15,2053.56 4072.81,2051.21 v1(4072.81,2033.06)
FPGA_CORECLK_p: C84.1 J1.G6 | length 1694.6
  Top Layer w10: C84.1@2627.65,1893.97 2627.65,1913.97 v1(2628.15,1913.97)
  L10 Ctrl Signal 2 w4: v1(2628.15,1913.97) 2628.15,1915.83 2620.67,1923.31 2620.67,1969.12 2668.55,2017 4011,2017 4022,2006 4093.73,2006 4114.51,2026.78 4114.51,2049.59 4101.54,2062.56 4075.15,2062.56 4072.81,2064.9 v1(4072.81,2083.06)
FPGA_SYSREF_n: C93.1 J1.G10 | length 1903.7
  Top Layer w10: C93.1@2637.72,1338.42 2637.72,1318.42 v1(2638.22,1318.42)
  L10 Ctrl Signal 2 w4: v1(2638.22,1318.42) 2633.09,1318.42 2630.74,1320.76 2630.74,1386.37 2684.38,1440 2731.4,1440 2876,1584.6 2876,1812.92 2933.38,1870.3 3806.82,1870.3 3840.07,1903.56 4070.47,1903.56 4072.81,1901.21 v1(4072.81,1883.06)
FPGA_SYSREF_p: C92.1 J1.G9 | length 1918.6
  Top Layer w10: v1(2614.27,1318.42) 2614.77,1318.42 C92.1@2614.77,1338.42
  L10 Ctrl Signal 2 w4: v1(2614.27,1318.42) 2619.4,1318.42 2621.74,1320.76 2621.74,1390.09 2680.65,1449 2727.67,1449 2867,1588.33 2867,1816.65 2929.66,1879.3 3803.09,1879.3 3836.34,1912.56 4070.47,1912.56 4072.81,1914.9 v1(4072.81,1933.06)
GA0_FMC: J1.C34 R213.2 U38.1 | length 744.3
  Top Layer w8: U38.1@4432.49,214.51 4454.49,214.51 4461.68,207.32 4461.68,205.36 4467.52,199.51 v1(4469.49,199.51)
  Bottom Layer w5: v1(4272.81,683.06) 4294.49,661.37 4294.49,629.02 4310.69,612.82 4485.37,612.82 4508.86,589.34 4508.86,346.35 4488.58,326.08 4488.58,218.61 v1(4469.49,199.51)
GA1_FMC: J1.D35 R214.2 U38.2 | length 643.3
  Top Layer w8: U38.2@4432.49,234.2 v1(4469.49,234.2)
  Bottom Layer w5: v1(4222.81,633.06) 4252.04,603.82 4431.81,603.82 4446.75,588.89 4446.75,350.84 4469.49,328.1 v1(4469.49,234.2)
GBTCLK0_FMC_n: C87.1 J1.D5 | length 1958.1
  Top Layer w10: v1(2521.4,1913.97) 2521.9,1913.97 C87.1@2521.9,1893.97
  L10 Ctrl Signal 2 w4: v1(2521.4,1913.97) 2521.4,1912.1 2528.87,1904.63 2528.87,1896.87 2541.44,1884.3 2897.77,1884.3 2970.4,1956.94 4111.12,1956.94 4147.81,1993.62 4147.81,2143.25 4158.11,2153.56 4220.47,2153.56 4222.81,2151.21 v1(4222.81,2133.06)
GBTCLK0_FMC_p: C86.1 J1.D4 | length 1943.2
  Top Layer w10: C86.1@2544.85,1893.97 2544.85,1913.97 v1(2545.35,1913.97)
  L10 Ctrl Signal 2 w4: v1(2545.35,1913.97) 2545.35,1912.1 2537.87,1904.63 2537.87,1900.6 2545.17,1893.3 2894.04,1893.3 2966.67,1965.94 4107.4,1965.94 4138.81,1997.35 4138.81,2146.98 4154.39,2162.56 4220.47,2162.56 4222.81,2164.9 v1(4222.81,2183.06)
GBTCLK1_FMC_n: C91.1 J1.B21 | length 2477.5
  Top Layer w10: C91.1@2554.93,1338.42 2554.93,1318.42 v1(2555.43,1318.42)
  L10 Ctrl Signal 2 w4: v1(2555.43,1318.42) 2550.29,1318.42 2547.95,1316.07 2547.95,1290.87 2559.69,1279.13 2698.05,1279.13 2938,1519.08 2938,1569.17 3057.83,1689 3571.15,1689 3649.21,1767.06 3946.85,1767.06 4148.54,1565.36 4307.36,1565.36 4316.36,1556.36 4406.67,1466.06 4406.67,1373.74 4386.48,1353.56 4325.15,1353.56 4322.81,1351.21 v1(4322.81,1333.06)
GBTCLK1_FMC_p: C90.1 J1.B20 | length 2462.6
  Top Layer w10: v1(2531.47,1318.42) 2531.97,1318.42 C90.1@2531.97,1338.42
  L10 Ctrl Signal 2 w4: v1(2531.47,1318.42) 2536.61,1318.42 2538.95,1316.07 2538.95,1287.14 2553.32,1272.77 2555.96,1270.13 2701.78,1270.13 2947,1515.35 2947,1565.44 3061.56,1680 3574.88,1680 3652.93,1758.06 3943.12,1758.06 4144.82,1556.36 4303.64,1556.36 4397.67,1462.33 4397.67,1377.47 4382.75,1362.56 4325.15,1362.56 4322.81,1364.9 v1(4322.81,1383.06)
